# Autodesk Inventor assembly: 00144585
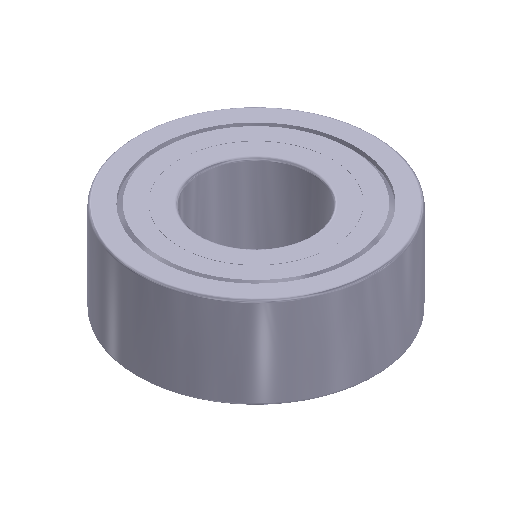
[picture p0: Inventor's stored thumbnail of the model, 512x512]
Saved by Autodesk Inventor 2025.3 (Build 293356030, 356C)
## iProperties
Created: 2021-02
Part Number: 00144585
Document SubType Name: Assembly
Designer: R5800u
Title: Radial/Deep Groove Ball Bearing, Round Bore, 6 mm ID, 13 mm OD, 5 mm Width, Double Shielded, CN Internal Clearance
Author: TraceParts
Sending System: SolidWorks 2021
Last Author: Albert
Last Saved: 2021-07-28
Closure_Type: Double Shielded
Maximum_RPM_Grease: 39000 rpm
Outer_Ring_Width: 5 mm
SUPPLIER: NTN Bearing Company
Inner_Ring_Width: 5 mm
REFERENCE: W686T2ZZ
Motion_Internal_Description: W686T2ZZ BALL BRG
Bearing_Material: High Carbon Chrome Steel
DESIGN: Radial/Deep Groove Ball Bearing, Round Bore, 6 mm ID, 13 mm OD, 5 mm Width, Double Shielded, CN Internal Clearance
Precision_Rating: ISO Class 0
Outside_Diameter: 13 mm
Finish_Coating: Uncoated
Part_Number_EShop_URL: https://motionindustries.com/products/sku/00144585
Internal_Clearance: CN
Fillet_Radius: 0.15 mm
SUPPLIER_PART_NUMBER: 00144585
SUPPLIER_NAME: Motion Industries
Weight: 0.01 lbs
Row_Type_Fill_Slot: Single Row Non-Fill Slot
Cage_Material: Steel
Snap_Ring_Included: Without Snap Ring
Overall_Width: 5 mm
Operating_Temperature_Range: -40 to 120 ºC
Bore_Diameter: 6 mm
Bore_Type: Round
TraceParts.PartStatus: Published
TraceParts.PartLanguage: en
TraceParts.PartTitle: Radial/Deep Groove Ball Bearing, W686T2ZZ
TraceParts.PartVersion: 1.0.0
TraceParts.PartNumber: 90-20102020-047584
TRACEPARTS: TRACEPARTS
TraceParts.ClassPath: MOTION_1402216426:90-20102020-047584
TraceParts.InstanceId: 90-20102020-0475842N3XX9WWY2MK673V115V3T3RA
TYPE: CATPART
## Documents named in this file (15)
- C:\Users\R5800u\Desktop\Nuova cartella (2)\Actuator\Actuator_movable\Actuator_movable\00144585.iam
- C:\Users\R5800u\Desktop\Nuova cartella (2)\Actuator\Actuator_movable\Actuator_movable\00144585_01.ipt
- C:\Users\R5800u\Desktop\Nuova cartella (2)\Actuator\Actuator_movable\Actuator_movable\00144585_02.ipt
- C:\Users\R5800u\Desktop\Nuova cartella (2)\Actuator\Actuator_movable\Actuator_movable\00144585_03.ipt
- C:\Users\R5800u\Desktop\Nuova cartella (2)\Actuator\Actuator_movable\Actuator_movable\00144585_04.ipt
- C:\Users\R5800u\Desktop\Nuova cartella (2)\Actuator\Actuator_movable\Actuator_movable\00144585_05.ipt
- C:\Users\R5800u\Desktop\Nuova cartella (2)\Actuator\Actuator_movable\Actuator_movable\00144585_06.ipt
- C:\Users\R5800u\Desktop\Nuova cartella (2)\Actuator\Actuator_movable\Actuator_movable\00144585_07.ipt
- C:\Users\R5800u\Desktop\Nuova cartella (2)\Actuator\Actuator_movable\Actuator_movable\00144585_08.ipt
- C:\Users\R5800u\Desktop\Nuova cartella (2)\Actuator\Actuator_movable\Actuator_movable\00144585_09.ipt
- C:\Users\R5800u\Desktop\Nuova cartella (2)\Actuator\Actuator_movable\Actuator_movable\00144585_10.ipt
- C:\Users\R5800u\Desktop\Nuova cartella (2)\Actuator\Actuator_movable\Actuator_movable\00144585_11.ipt
- C:\Users\R5800u\Desktop\Nuova cartella (2)\Actuator\Actuator_movable\Actuator_movable\00144585_12.ipt
- C:\Users\R5800u\Desktop\Nuova cartella (2)\Actuator\Actuator_movable\Actuator_movable\00144585_13.ipt
- C:\Users\R5800u\Desktop\Nuova cartella (2)\Actuator\Actuator_movable\Actuator_movable\00144585_14.ipt
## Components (14 placed, 14 different names)
1. 00144585_01:1
2. 00144585_02:1
3. 00144585_03:1
4. 00144585_04:1
5. 00144585_05:1
6. 00144585_06:1
7. 00144585_07:1
8. 00144585_08:1
9. 00144585_09:1
10. 00144585_10:1
11. 00144585_11:1
12. 00144585_12:1
13. 00144585_13:1
14. 00144585_14:1
